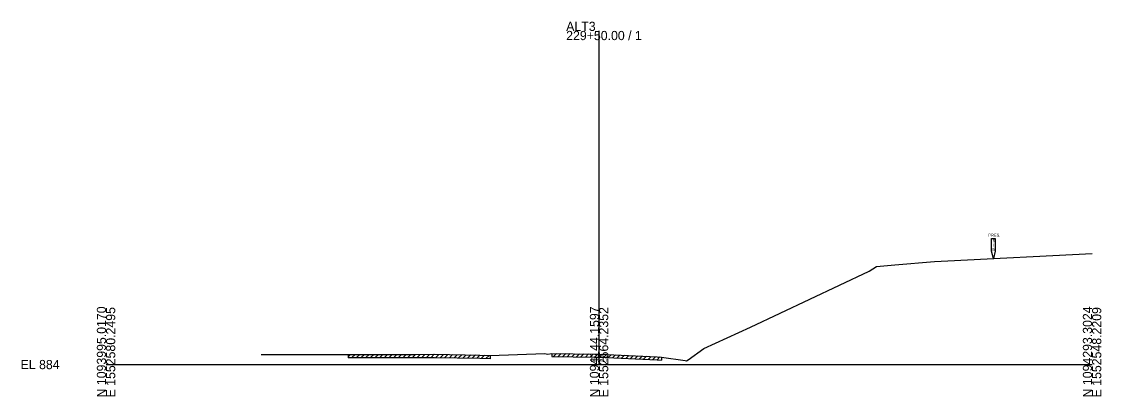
# Model space of a CAD drawing. Extents: x -26 to 1303, y -10 to 19582.
# Drawn here: x -25.7 to 302.8, y 2990.3 to 3104.4 of the extents above; entities that cross this region are included whole.
import ezdxf

# ---------------------------------------------------------------- set-up
doc = ezdxf.new("R2010")
doc.units = 0
for name, color, linetype in [('Default', 7, 'Continuous'), ('RD_GPK_XS_Cell', 7, 'Continuous'), ('RD_XS_ExGround', 7, 'Continuous'), ('RD_XS_ExPaveRet', 7, 'Continuous'), ('RD_XS_ExRW', 7, 'Continuous'), ('RD_XS_TX_Elev_EX', 7, 'Continuous')]:
    doc.layers.add(name, color=color, linetype=linetype)

msp = doc.modelspace()

# ---------------------------------------------------------------- linework, layer by layer
at = {"layer": 'RD_GPK_XS_Cell'}
for p, q in [((150, 3000), (150, 3101.53)), ((0, 3000), (150, 3000)), ((150, 3000), (300, 3000))]:
    msp.add_line(p, q, dxfattribs=at)
at = {"layer": 'RD_XS_ExGround'}
msp.add_lwpolyline([(47.19, 3003.02), (49.41, 3003.03), (73.69, 3003.07), (94.06, 3003.08), (99.91, 3003.12), (113.73, 3002.89), (116.89, 3002.79), (133.5, 3003.32), (134.33, 3003.2), (135.64, 3003.41), (148.67, 3003.19), (150.13, 3003.17), (167.67, 3002.37), (169.04, 3002.29), (176.18, 3001.22), (176.56, 3001.15), (177.12, 3001.46), (181.92, 3004.92), (196.04, 3011.41), (232.18, 3028.41), (234.45, 3029.89), (240.02, 3030.35), (252.01, 3031.41), (256.14, 3031.59), (300, 3033.84)], dxfattribs=at)
at = {"layer": 'RD_XS_ExPaveRet'}
for p, q in [((73.69, 3003.07), (73.69, 3002.07)), ((73.69, 3002.4), (74.36, 3003.07)), ((74.82, 3002.12), (75.77, 3003.07)), ((76.24, 3002.12), (77.19, 3003.07)), ((77.65, 3002.12), (78.6, 3003.07)), ((79.07, 3002.12), (80.02, 3003.07)), ((80.48, 3002.12), (81.43, 3003.07)), ((81.9, 3002.12), (82.85, 3003.08)), ((83.31, 3002.13), (84.26, 3003.08)), ((84.73, 3002.13), (85.68, 3003.08)), ((86.14, 3002.13), (87.09, 3003.08)), ((87.55, 3002.13), (88.51, 3003.08)), ((88.97, 3002.13), (89.92, 3003.08)), ((90.38, 3002.13), (91.33, 3003.08)), ((91.8, 3002.13), (92.75, 3003.08)), ((93.21, 3002.13), (94.16, 3003.08)), ((94.63, 3002.13), (95.59, 3003.09)), ((96.06, 3002.14), (97.01, 3003.1)), ((97.48, 3002.15), (98.44, 3003.11)), ((98.91, 3002.17), (99.87, 3003.12)), ((100.32, 3002.17), (101.26, 3003.1)), ((101.71, 3002.14), (102.65, 3003.08)), ((103.1, 3002.12), (104.04, 3003.05)), ((104.49, 3002.09), (105.43, 3003.03)), ((105.88, 3002.07), (106.82, 3003)), ((107.27, 3002.05), (108.21, 3002.98)), ((108.66, 3002.02), (109.6, 3002.96)), ((110.05, 3002), (110.99, 3002.93)), ((111.44, 3001.97), (112.38, 3002.91)), ((112.83, 3001.95), (113.77, 3002.88)), ((114.22, 3001.92), (115.14, 3002.84)), ((115.59, 3001.88), (116.52, 3002.8)), ((116.89, 3002.79), (116.89, 3001.79)), ((135.64, 3003.41), (135.64, 3002.41)), ((135.64, 3003.38), (135.67, 3003.41)), ((136.13, 3002.45), (137.06, 3003.38)), ((137.52, 3002.43), (138.46, 3003.36)), ((138.91, 3002.4), (139.85, 3003.34)), ((140.3, 3002.38), (141.24, 3003.32)), ((141.69, 3002.36), (142.63, 3003.29)), ((143.09, 3002.33), (144.02, 3003.27)), ((144.48, 3002.31), (145.41, 3003.25)), ((145.87, 3002.29), (146.8, 3003.22)), ((147.26, 3002.27), (148.19, 3003.2)), ((148.65, 3002.24), (149.59, 3003.18)), ((150.04, 3002.22), (150.95, 3003.13)), ((151.4, 3002.16), (152.31, 3003.07)), ((152.75, 3002.1), (153.66, 3003.01)), ((154.1, 3002.04), (155.01, 3002.95)), ((155.45, 3001.98), (156.36, 3002.88)), ((156.81, 3001.91), (157.72, 3002.82)), ((158.16, 3001.85), (159.07, 3002.76)), ((159.51, 3001.79), (160.42, 3002.7)), ((160.86, 3001.73), (161.77, 3002.64)), ((162.22, 3001.67), (163.13, 3002.58)), ((163.57, 3001.6), (164.48, 3002.51)), ((164.92, 3001.54), (165.83, 3002.45)), ((166.27, 3001.48), (167.18, 3002.39)), ((167.63, 3001.42), (168.53, 3002.32)), ((168.97, 3001.35), (169.04, 3001.42)), ((169.04, 3002.29), (169.04, 3001.29))]:
    msp.add_line(p, q, dxfattribs=at)
for points in [[(73.69, 3002.12), (94.03, 3002.13), (99.91, 3002.17), (113.71, 3001.93), (116.89, 3001.84)], [(135.64, 3002.46), (148.65, 3002.24), (150.13, 3002.22), (167.65, 3001.42), (169.04, 3001.34)]]:
    msp.add_lwpolyline(points, dxfattribs=at)
at = {"layer": 'RD_XS_ExRW'}
msp.add_lwpolyline([(269.45, 3038.32), (270.55, 3038.32), (270.55, 3034.49), (270, 3032.3), (269.45, 3034.49)], close=True, dxfattribs=at)

# ---------------------------------------------------------------- texts
at = {"layer": 'Default'}
msp.add_text('-', height=0.0001, dxfattribs=at).set_placement((0, 3000))
at = {"layer": 'RD_GPK_XS_Cell'}
for s, p in [('ALT3', (140, 3101.53)), ('229+50.00 / 1', (140, 3098.73)), ('EL 884', (-26, 2998.6))]:
    msp.add_text(s, height=2.8, dxfattribs=at).set_placement(p)
for s, p in [('N 1093995.0170', (0, 2990)), ('E 1552580.2495', (2.8, 2990)), ('N 1094144.1597', (150, 2990)), ('E 1552564.2352', (152.8, 2990)), ('N 1094293.3024', (300, 2990)), ('E 1552548.2209', (302.8, 2990))]:
    msp.add_text(s, height=2.8, rotation=90, dxfattribs=at).set_placement(p)
at = {"layer": 'RD_XS_ExRW'}
for s, p in [('PRES.', (268.45, 3038.94)), ('R', (269.71, 3037.23)), ('/', (269.83, 3035.91)), ('W', (269.53, 3034.6))]:
    msp.add_text(s, height=0.875, dxfattribs=at).set_placement(p)
at = {"layer": 'RD_XS_TX_Elev_EX'}
msp.add_text('887.17', height=1.25, dxfattribs=at).set_placement((147.45, 3000.75))

doc.saveas('drawing.dxf')
